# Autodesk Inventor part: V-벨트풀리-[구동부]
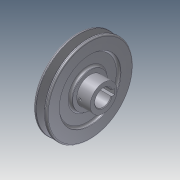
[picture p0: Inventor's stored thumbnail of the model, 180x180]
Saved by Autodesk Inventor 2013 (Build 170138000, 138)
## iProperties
Company: 한국ATC센터
Created: 2014-10
Part Number: V-벨트풀리-[구동부]
Document SubType Name: Modeling
Designer: 한국ATC센터
Density: 7.86 g/cm^3
Material: 강, 연강
Mass: 1515.01 g
Surface Area: 468.111 cm^2
Volume: 192.75 cm^3
Author: KYOUNG IL JANG
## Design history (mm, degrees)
sketch "스케치1"
  geometry: L1 (-20, 0)-(20, 0); L2 (-20, 0)-(-20, 26); L3 (-20, 26)-(-16, 26); L4 (-16, 26)-(-16, 46); L5 (-16, 46)-(-20, 46); L6 (-20, 46)-(-20, 64.5); L7 (-20, 64.5)-(-16.062, 64.5); L8 (-16.062, 64.5)-(-12.001, 52); L9 (-12.001, 52)-(-7.999, 52); L10 (-7.999, 52)-(-3.938, 64.5); L11 (-3.938, 64.5)-(0, 64.5); L12 (0, 64.5)-(0, 46); L13 (0, 46)-(-4, 46); L14 (-4, 46)-(-4, 26); L15 (-4, 26)-(0, 26); L16 (0, 26)-(0, 20); L17 (0, 20)-(20, 20); L18 (20, 20)-(20, 0); L19 (-14.6, 60)-(-5.4, 60); 2 further points
  constraints: 38 end point, 11 parallel, 7 collinear, 3 equal length, 3 perpendicular, 2 point on line, 1 coincident, 1 horizontal, 1 midpoint
  dimensions: "d0" = 40 distance of L1.start L1.end; "d1" = 4.5 distance between parallel lines of L7 L19; "d2" = 8 distance between parallel lines of L9 L19; "d3" = 9.2 distance of L19.start L19.end; "d4" = 36 deg angle of L10 L8; "d5" = 20 distance between parallel lines of L12 L6; "d6" = 120 diameter of L19 L1; "d7" = 4 distance of L2.end L3.end; "d8" = 52 diameter of L3 L1; "d9" = 92 diameter of L5 L1; "d10" = 40 diameter of L17 L1
revolve "회전1" sketch "스케치1" stored, may be unused: angle "d11" = 90 deg
sketch "스케치2"
  geometry: L1 (-4, 11.843)-(-4, 16.5); L2 (-4, 16.5)-(4, 16.5); L3 (4, 16.5)-(4, 11.843); A1 r 12.5 centre (0, 0) between (-4, 11.843) and (4, 11.843); 1 further point
  constraints: 6 end point, 2 parallel, 2 point on circle, 1 centre point, 1 coincident, 1 horizontal, 1 vertical
  dimensions: "d12" = 25 diameter of A1; "d13" = 8 distance of L1.end L2.end; "d14" = 29 dimension on A1 L2
extrude "돌출1" cut sketch "스케치2" stored distance "d15" = 10; taper "d16" = 0 deg
chamfer "모따기1" distance "d17" = 1; stored, may be unused: second distance "d18" = 2, angle "d19" = 45 deg
node "작업 평면1"
sketch "스케치3"
  geometry: L1 (10, -20)-(10, 20) reference; 3 further points
  constraints: 1 horizontal alignment, 1 midpoint
  dimensions: "d20" = 15 distance from line of L1 point (-5, 0)
hole "구멍1" sketch "스케치3" at (-5, 0) diameter "d21" = 4.459; stored, may be unused: countersink angle "d25" = 90 deg, drill point angle "d27" = 118 deg; dims "d22" = 6, "d23" = 4, "d24" = 2, "d26" = 8
fillet "모깎기1" dims "d28" = 3, "d29" = 2, "d30" = 0.5, "d31" = 1
node "솔리드1"
